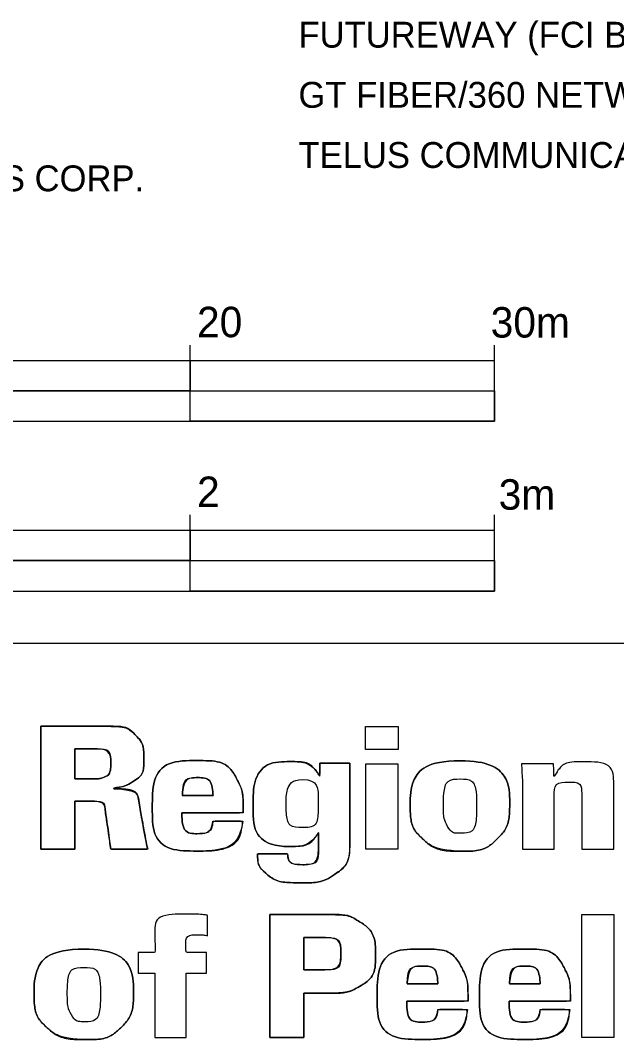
# Model space of a CAD drawing. Extents: x 613360 to 613780, y 4825621 to 4825911.
# Drawn here: x 613737.07 to 613756.65, y 4825658.5 to 4825691.97 of the extents above; entities that cross this region are included whole.
import ezdxf

# ---------------------------------------------------------------- set-up
doc = ezdxf.new("R2010")
doc.units = 0
for name, color, linetype in [('G-ANNO-BAR', 7, 'Continuous'), ('G-ANNO-TEXT', 7, 'Continuous'), ('G-TTLB-LOGO', 7, 'Continuous'), ('G-TTLB-OTLN', 7, 'Continuous')]:
    doc.layers.add(name, color=color, linetype=linetype)

msp = doc.modelspace()

# ---------------------------------------------------------------- linework, layer by layer
at = {"layer": 'G-ANNO-BAR'}
for p, q in [((613742.645, 4825678.805), (613742.645, 4825681.305)), ((613752.645, 4825678.805), (613752.645, 4825681.305)), ((613712.645, 4825680.805), (613752.645, 4825680.805)), ((613712.645, 4825679.805), (613752.645, 4825679.805)), ((613712.645, 4825678.805), (613752.645, 4825678.805)), ((613742.646, 4825673.229), (613742.646, 4825675.729)), ((613752.646, 4825673.229), (613752.646, 4825675.729)), ((613712.646, 4825675.229), (613752.646, 4825675.229)), ((613712.646, 4825674.229), (613752.646, 4825674.229)), ((613712.646, 4825673.229), (613752.646, 4825673.229))]:
    msp.add_line(p, q, dxfattribs=at)
for points in [[(613732.645, 4825680.805), (613742.645, 4825680.805), (613742.645, 4825679.805), (613732.645, 4825679.805)], [(613742.645, 4825679.805), (613752.645, 4825679.805), (613752.645, 4825678.805), (613742.645, 4825678.805)], [(613732.646, 4825675.229), (613742.646, 4825675.229), (613742.646, 4825674.229), (613732.646, 4825674.229)], [(613742.646, 4825674.229), (613752.646, 4825674.229), (613752.646, 4825673.229), (613742.646, 4825673.229)]]:
    msp.add_lwpolyline(points, close=True, dxfattribs=at)
at = {"layer": 'G-TTLB-LOGO'}
for p, q in [((613748.408, 4825668.781), (613749.482, 4825668.781)), ((613748.408, 4825668.032), (613748.408, 4825668.781)), ((613749.482, 4825668.781), (613749.482, 4825668.032)), ((613749.482, 4825668.032), (613748.408, 4825668.032)), ((613748.419, 4825667.562), (613749.47, 4825667.562)), ((613748.419, 4825664.754), (613748.419, 4825667.562)), ((613749.47, 4825667.562), (613749.47, 4825664.754)), ((613740.143, 4825666.762), (613740.143, 4825666.74)), ((613742.387, 4825666.516), (613743.399, 4825666.516)), ((613744.389, 4825665.946), (613742.375, 4825665.946)), ((613743.393, 4825665.672), (613744.372, 4825665.672)), ((613746.865, 4825664.928), (613746.865, 4825665.297)), ((613741.251, 4825664.754), (613740.037, 4825664.754)), ((613744.857, 4825664.604), (613745.847, 4825664.604)), ((613749.47, 4825664.754), (613748.419, 4825664.754)), ((613755.504, 4825662.605), (613756.556, 4825662.605)), ((613755.504, 4825658.567), (613755.504, 4825662.605)), ((613756.556, 4825662.605), (613756.556, 4825658.567)), ((613749.77, 4825660.329), (613750.782, 4825660.329)), ((613753.132, 4825660.329), (613754.144, 4825660.329)), ((613751.772, 4825659.758), (613749.759, 4825659.758)), ((613755.134, 4825659.758), (613753.12, 4825659.758)), ((613750.777, 4825659.484), (613751.756, 4825659.484)), ((613754.138, 4825659.484), (613755.117, 4825659.484)), ((613756.556, 4825658.567), (613755.504, 4825658.567))]:
    msp.add_line(p, q, dxfattribs=at)
for points in [[(613739.332, 4825666.332), (613738.862, 4825666.332), (613738.862, 4825664.754), (613737.738, 4825664.754), (613737.738, 4825668.792), (613739.606, 4825668.792)], [(613748.408, 4825668.781), (613749.482, 4825668.781), (613749.482, 4825668.032), (613748.408, 4825668.032), (613748.408, 4825668.781)], [(613739.282, 4825668.049), (613738.862, 4825668.049), (613738.862, 4825667.059), (613739.282, 4825667.059)], [(613746.899, 4825667.154), (613746.899, 4825667.579), (613747.889, 4825667.579), (613747.889, 4825664.961)], [(613748.419, 4825667.562), (613749.47, 4825667.562), (613749.47, 4825664.754), (613748.419, 4825664.754), (613748.419, 4825667.562)], [(613747.108, 4825660.027), (613746.381, 4825660.021), (613746.381, 4825658.567), (613745.257, 4825658.567), (613745.257, 4825662.605), (613747.113, 4825662.605)], [(613755.504, 4825662.605), (613756.556, 4825662.605), (613756.556, 4825658.567), (613755.504, 4825658.567), (613755.504, 4825662.605)], [(613746.873, 4825661.855), (613746.381, 4825661.855), (613746.381, 4825660.793), (613746.878, 4825660.793)]]:
    msp.add_lwpolyline(points, dxfattribs=at)
for points in [[(613737.738, 4825668.792), (613737.738, 4825668.792), (613739.606, 4825668.792), (613739.606, 4825668.792), (613740.333, 4825668.792), (613740.607, 4825668.748), (613740.848, 4825668.502), (613740.971, 4825668.378), (613741.127, 4825668.155), (613741.127, 4825667.719), (613741.127, 4825667.277), (613740.949, 4825667.086), (613740.758, 4825666.969), (613740.501, 4825666.807), (613740.255, 4825666.779), (613740.143, 4825666.762), (613740.143, 4825666.762), (613740.143, 4825666.74), (613740.143, 4825666.74), (613740.926, 4825666.717), (613740.942, 4825666.373), (613741.06, 4825665.75), (613741.112, 4825665.478), (613741.202, 4825664.949), (613741.251, 4825664.754), (613741.251, 4825664.754), (613740.037, 4825664.754), (613740.037, 4825664.754), (613740.017, 4825664.897), (613739.96, 4825665.318), (613739.913, 4825665.628), (613739.84, 4825666.112), (613739.836, 4825666.332), (613739.332, 4825666.332), (613739.332, 4825666.332), (613738.862, 4825666.332), (613738.862, 4825666.332), (613738.862, 4825666.332), (613738.862, 4825664.754), (613738.862, 4825664.754), (613738.862, 4825664.754), (613737.738, 4825664.754), (613737.738, 4825664.754), (613737.738, 4825664.754), (613737.738, 4825668.792), (613737.738, 4825668.792)], [(613739.606, 4825668.792), (613740.333, 4825668.792), (613740.607, 4825668.748), (613740.848, 4825668.502), (613740.971, 4825668.378), (613741.127, 4825668.155), (613741.127, 4825667.719), (613741.127, 4825667.277), (613740.949, 4825667.086), (613740.758, 4825666.969), (613740.501, 4825666.807), (613740.255, 4825666.779), (613740.143, 4825666.762)], [(613738.862, 4825667.059), (613738.862, 4825667.059), (613739.282, 4825667.059), (613739.282, 4825667.059), (613739.528, 4825667.059), (613739.651, 4825667.059), (613739.746, 4825667.092), (613739.992, 4825667.17), (613740.043, 4825667.422), (613740.043, 4825667.551), (613740.043, 4825668.049), (613739.606, 4825668.049), (613739.282, 4825668.049), (613739.282, 4825668.049), (613738.862, 4825668.049), (613738.862, 4825668.049), (613738.862, 4825668.049), (613738.862, 4825667.059), (613738.862, 4825667.059)], [(613739.282, 4825667.059), (613739.528, 4825667.059), (613739.651, 4825667.059), (613739.746, 4825667.092), (613739.992, 4825667.17), (613740.043, 4825667.422), (613740.043, 4825667.551), (613740.043, 4825668.049), (613739.606, 4825668.049), (613739.282, 4825668.049)], [(613742.375, 4825665.946), (613742.375, 4825665.794), (613742.375, 4825665.263), (613742.912, 4825665.263), (613743.192, 4825665.263), (613743.365, 4825665.409), (613743.393, 4825665.672), (613743.393, 4825665.672), (613744.372, 4825665.672), (613744.372, 4825665.672), (613744.294, 4825664.967), (613743.634, 4825664.693), (613742.907, 4825664.693), (613741.928, 4825664.693), (613741.402, 4825665.185), (613741.402, 4825666.114), (613741.402, 4825667.053), (613741.861, 4825667.663), (613742.896, 4825667.663), (613743.678, 4825667.663), (613744.042, 4825667.344), (613744.232, 4825666.947), (613744.355, 4825666.706), (613744.389, 4825666.438), (613744.389, 4825665.946), (613744.389, 4825665.946), (613742.375, 4825665.946), (613742.375, 4825665.946)], [(613744.372, 4825665.672), (613744.294, 4825664.967), (613743.634, 4825664.693), (613742.907, 4825664.693), (613741.928, 4825664.693), (613741.402, 4825665.185), (613741.402, 4825666.114), (613741.402, 4825667.053), (613741.861, 4825667.663), (613742.896, 4825667.663), (613743.678, 4825667.663), (613744.042, 4825667.344), (613744.232, 4825666.947), (613744.355, 4825666.706), (613744.389, 4825666.438), (613744.389, 4825665.946)], [(613747.889, 4825667.579), (613747.889, 4825667.579), (613747.889, 4825664.961), (613747.889, 4825664.961), (613747.889, 4825664.626), (613747.822, 4825664.229), (613747.441, 4825663.96), (613747.201, 4825663.787), (613746.86, 4825663.647), (613746.284, 4825663.647), (613745.965, 4825663.647), (613745.433, 4825663.692), (613745.115, 4825663.977), (613744.869, 4825664.195), (613744.863, 4825664.458), (613744.857, 4825664.604), (613744.857, 4825664.604), (613745.847, 4825664.604), (613745.847, 4825664.604), (613745.853, 4825664.391), (613746.004, 4825664.245), (613746.306, 4825664.245), (613746.832, 4825664.245), (613746.865, 4825664.626), (613746.865, 4825664.928), (613746.865, 4825664.928), (613746.865, 4825665.297), (613746.865, 4825665.297), (613746.58, 4825664.872), (613746.121, 4825664.844), (613745.959, 4825664.844), (613745.366, 4825664.844), (613744.712, 4825665.213), (613744.712, 4825666.236), (613744.712, 4825666.997), (613745.115, 4825667.629), (613745.97, 4825667.629), (613746.513, 4825667.629), (613746.759, 4825667.377), (613746.899, 4825667.154), (613746.899, 4825667.154), (613746.899, 4825667.579), (613746.899, 4825667.579), (613746.899, 4825667.579), (613747.889, 4825667.579), (613747.889, 4825667.579)], [(613746.865, 4825665.297), (613746.58, 4825664.872), (613746.121, 4825664.844), (613745.959, 4825664.844), (613745.366, 4825664.844), (613744.712, 4825665.213), (613744.712, 4825666.236), (613744.712, 4825666.997), (613745.115, 4825667.629), (613745.97, 4825667.629), (613746.513, 4825667.629), (613746.759, 4825667.377), (613746.899, 4825667.154)], [(613751.518, 4825667.657), (613752.43, 4825667.657), (613753.14, 4825667.198), (613753.14, 4825666.203), (613753.14, 4825665.794), (613753.023, 4825665.381), (613752.732, 4825665.09), (613752.497, 4825664.861), (613752.15, 4825664.687), (613751.574, 4825664.687), (613750.953, 4825664.687), (613750.551, 4825664.838), (613750.277, 4825665.101), (613749.952, 4825665.409), (613749.874, 4825665.828), (613749.874, 4825666.169), (613749.874, 4825667.031), (613750.405, 4825667.657), (613751.518, 4825667.657)], [(613751.218, 4825664.706), (613750.793, 4825664.754), (613750.495, 4825664.892), (613750.277, 4825665.101), (613749.952, 4825665.409), (613749.874, 4825665.828), (613749.874, 4825666.169), (613749.874, 4825667.031), (613750.405, 4825667.657), (613751.518, 4825667.657)], [(613751.518, 4825667.657), (613752.43, 4825667.657), (613753.14, 4825667.198), (613753.14, 4825666.203), (613753.14, 4825665.794), (613753.023, 4825665.381), (613752.732, 4825665.09), (613752.497, 4825664.861), (613752.15, 4825664.687), (613751.574, 4825664.687), (613751.447, 4825664.687), (613751.328, 4825664.694), (613751.218, 4825664.706)], [(613753.558, 4825666.964), (613753.558, 4825666.964), (613753.53, 4825667.562), (613753.53, 4825667.562), (613753.53, 4825667.562), (613754.581, 4825667.562), (613754.581, 4825667.562), (613754.581, 4825667.562), (613754.593, 4825667.131), (613754.593, 4825667.131), (613754.721, 4825667.344), (613754.945, 4825667.623), (613755.527, 4825667.623), (613756.556, 4825667.623), (613756.556, 4825666.841), (613756.556, 4825666.454), (613756.556, 4825666.454), (613756.556, 4825664.754), (613756.556, 4825664.754), (613756.556, 4825664.754), (613755.504, 4825664.754), (613755.504, 4825664.754), (613755.504, 4825664.754), (613755.504, 4825666.365), (613755.504, 4825666.365), (613755.504, 4825666.561), (613755.504, 4825666.958), (613755.074, 4825666.958), (613754.604, 4825666.958), (613754.604, 4825666.466), (613754.604, 4825666.365), (613754.604, 4825666.365), (613754.604, 4825664.754), (613754.604, 4825664.754), (613754.604, 4825664.754), (613753.558, 4825664.754), (613753.558, 4825664.754), (613753.558, 4825664.754), (613753.558, 4825666.964), (613753.558, 4825666.964)], [(613753.558, 4825666.964), (613753.558, 4825666.964), (613753.53, 4825667.562), (613753.53, 4825667.562), (613753.53, 4825667.562), (613754.581, 4825667.562), (613754.581, 4825667.562), (613754.581, 4825667.562), (613754.593, 4825667.131), (613754.593, 4825667.131), (613754.721, 4825667.344), (613754.945, 4825667.623), (613755.527, 4825667.623), (613756.556, 4825667.623), (613756.556, 4825666.841), (613756.556, 4825666.454), (613756.556, 4825666.454), (613756.556, 4825664.754), (613756.556, 4825664.754), (613756.556, 4825664.754), (613755.504, 4825664.754), (613755.504, 4825664.754), (613755.504, 4825664.754), (613755.504, 4825666.365), (613755.504, 4825666.365), (613755.504, 4825666.561), (613755.504, 4825666.958), (613755.074, 4825666.958), (613754.604, 4825666.958), (613754.604, 4825666.466), (613754.604, 4825666.365), (613754.604, 4825666.365), (613754.604, 4825664.754), (613754.604, 4825664.754), (613754.604, 4825664.754), (613753.558, 4825664.754), (613753.558, 4825664.754), (613753.558, 4825664.754), (613753.558, 4825666.964), (613753.558, 4825666.964)], [(613743.399, 4825666.516), (613743.388, 4825666.678), (613743.354, 4825667.103), (613742.896, 4825667.103), (613742.437, 4825667.103), (613742.398, 4825666.65), (613742.387, 4825666.516), (613742.387, 4825666.516), (613743.399, 4825666.516), (613743.399, 4825666.516)], [(613743.399, 4825666.516), (613743.388, 4825666.678), (613743.354, 4825667.103), (613742.896, 4825667.103), (613742.437, 4825667.103), (613742.398, 4825666.65), (613742.387, 4825666.516)], [(613746.339, 4825667.042), (613745.987, 4825667.042), (613745.797, 4825666.717), (613745.797, 4825666.248), (613745.797, 4825665.951), (613745.864, 4825665.465), (613746.328, 4825665.465), (613746.832, 4825665.465), (613746.849, 4825666.057), (613746.849, 4825666.259), (613746.849, 4825666.404), (613746.849, 4825667.042), (613746.339, 4825667.042)], [(613746.339, 4825667.042), (613745.987, 4825667.042), (613745.797, 4825666.717), (613745.797, 4825666.248), (613745.797, 4825665.951), (613745.864, 4825665.465), (613746.328, 4825665.465), (613746.832, 4825665.465), (613746.849, 4825666.057), (613746.849, 4825666.259), (613746.849, 4825666.404), (613746.849, 4825667.042), (613746.339, 4825667.042)], [(613751.099, 4825665.498), (613751.222, 4825665.286), (613751.412, 4825665.275), (613751.507, 4825665.275), (613751.966, 4825665.275), (613752.055, 4825665.772), (613752.055, 4825666.164), (613752.055, 4825666.65), (613751.938, 4825667.059), (613751.518, 4825667.059), (613751.054, 4825667.059), (613750.965, 4825666.583), (613750.965, 4825666.164), (613750.965, 4825665.979), (613750.981, 4825665.705), (613751.099, 4825665.498)], [(613751.099, 4825665.498), (613751.222, 4825665.286), (613751.412, 4825665.275), (613751.507, 4825665.275), (613751.966, 4825665.275), (613752.055, 4825665.772), (613752.055, 4825666.164), (613752.055, 4825666.65), (613751.938, 4825667.059), (613751.518, 4825667.059), (613751.054, 4825667.059), (613750.965, 4825666.583), (613750.965, 4825666.164), (613750.965, 4825665.979), (613750.981, 4825665.705), (613751.099, 4825665.498)], [(613740.143, 4825666.74), (613740.926, 4825666.717), (613740.942, 4825666.373), (613741.06, 4825665.75), (613741.112, 4825665.478), (613741.202, 4825664.949), (613741.251, 4825664.754)], [(613740.037, 4825664.754), (613740.017, 4825664.897), (613739.96, 4825665.318), (613739.913, 4825665.628), (613739.84, 4825666.112), (613739.836, 4825666.332), (613739.332, 4825666.332)], [(613742.375, 4825665.946), (613742.375, 4825665.794), (613742.375, 4825665.263), (613742.912, 4825665.263), (613743.192, 4825665.263), (613743.365, 4825665.409), (613743.393, 4825665.672)], [(613747.889, 4825664.961), (613747.889, 4825664.626), (613747.822, 4825664.229), (613747.441, 4825663.96), (613747.201, 4825663.787), (613746.86, 4825663.647), (613746.284, 4825663.647), (613745.965, 4825663.647), (613745.433, 4825663.692), (613745.115, 4825663.977), (613744.869, 4825664.195), (613744.863, 4825664.458), (613744.857, 4825664.604)], [(613745.847, 4825664.604), (613745.853, 4825664.391), (613746.004, 4825664.245), (613746.306, 4825664.245), (613746.832, 4825664.245), (613746.865, 4825664.626), (613746.865, 4825664.928)], [(613743.215, 4825661.911), (613743.17, 4825661.923), (613743.064, 4825661.945), (613742.924, 4825661.945), (613742.493, 4825661.945), (613742.505, 4825661.598), (613742.51, 4825661.363), (613742.51, 4825661.363), (613743.187, 4825661.363), (613743.187, 4825661.363), (613743.187, 4825661.363), (613743.187, 4825660.681), (613743.187, 4825660.681), (613743.187, 4825660.681), (613742.51, 4825660.681), (613742.51, 4825660.681), (613742.51, 4825660.681), (613742.51, 4825658.567), (613742.51, 4825658.567), (613742.51, 4825658.567), (613741.481, 4825658.567), (613741.481, 4825658.567), (613741.481, 4825658.567), (613741.481, 4825660.681), (613741.481, 4825660.681), (613741.481, 4825660.681), (613740.939, 4825660.681), (613740.939, 4825660.681), (613740.939, 4825660.681), (613740.939, 4825661.363), (613740.939, 4825661.363), (613740.939, 4825661.363), (613741.498, 4825661.363), (613741.498, 4825661.363), (613741.481, 4825662.034), (613741.493, 4825662.622), (613742.594, 4825662.622), (613742.88, 4825662.622), (613743.098, 4825662.599), (613743.215, 4825662.588), (613743.215, 4825662.588), (613743.215, 4825661.911), (613743.215, 4825661.911)], [(613743.215, 4825661.911), (613743.17, 4825661.923), (613743.064, 4825661.945), (613742.924, 4825661.945), (613742.493, 4825661.945), (613742.505, 4825661.598), (613742.51, 4825661.363), (613742.51, 4825661.363), (613743.187, 4825661.363), (613743.187, 4825661.363), (613743.187, 4825661.363), (613743.187, 4825660.681), (613743.187, 4825660.681), (613743.187, 4825660.681), (613742.51, 4825660.681), (613742.51, 4825660.681), (613742.51, 4825660.681), (613742.51, 4825658.567), (613742.51, 4825658.567), (613742.51, 4825658.567), (613741.481, 4825658.567), (613741.481, 4825658.567), (613741.481, 4825658.567), (613741.481, 4825660.681), (613741.481, 4825660.681), (613741.481, 4825660.681), (613740.939, 4825660.681), (613740.939, 4825660.681), (613740.939, 4825660.681), (613740.939, 4825661.363), (613740.939, 4825661.363), (613740.939, 4825661.363), (613741.498, 4825661.363), (613741.498, 4825661.363), (613741.481, 4825662.034), (613741.493, 4825662.622), (613742.594, 4825662.622), (613742.88, 4825662.622), (613743.098, 4825662.599), (613743.215, 4825662.588), (613743.215, 4825662.588), (613743.215, 4825661.911), (613743.215, 4825661.911)], [(613745.257, 4825662.605), (613745.257, 4825662.605), (613747.113, 4825662.605), (613747.113, 4825662.605), (613747.427, 4825662.605), (613747.835, 4825662.605), (613748.165, 4825662.398), (613748.506, 4825662.191), (613748.735, 4825661.828), (613748.735, 4825661.302), (613748.735, 4825660.592), (613748.282, 4825660.284), (613748.126, 4825660.2), (613747.812, 4825660.027), (613747.326, 4825660.027), (613747.108, 4825660.027), (613747.108, 4825660.027), (613746.381, 4825660.021), (613746.381, 4825660.021), (613746.381, 4825660.021), (613746.381, 4825658.567), (613746.381, 4825658.567), (613746.381, 4825658.567), (613745.257, 4825658.567), (613745.257, 4825658.567), (613745.257, 4825658.567), (613745.257, 4825662.605), (613745.257, 4825662.605)], [(613747.113, 4825662.605), (613747.427, 4825662.605), (613747.835, 4825662.605), (613748.165, 4825662.398), (613748.506, 4825662.191), (613748.735, 4825661.828), (613748.735, 4825661.302), (613748.735, 4825660.592), (613748.282, 4825660.284), (613748.126, 4825660.2), (613747.812, 4825660.027), (613747.326, 4825660.027), (613747.108, 4825660.027)], [(613746.381, 4825660.793), (613746.381, 4825660.793), (613746.878, 4825660.793), (613746.878, 4825660.793), (613747.153, 4825660.793), (613747.594, 4825660.793), (613747.594, 4825661.335), (613747.594, 4825661.828), (613747.197, 4825661.855), (613746.873, 4825661.855), (613746.873, 4825661.855), (613746.381, 4825661.855), (613746.381, 4825661.855), (613746.381, 4825661.855), (613746.381, 4825660.793), (613746.381, 4825660.793)], [(613746.878, 4825660.793), (613747.153, 4825660.793), (613747.594, 4825660.793), (613747.594, 4825661.335), (613747.594, 4825661.828), (613747.197, 4825661.855), (613746.873, 4825661.855)], [(613739.164, 4825661.469), (613740.076, 4825661.469), (613740.786, 4825661.011), (613740.786, 4825660.016), (613740.786, 4825659.607), (613740.669, 4825659.193), (613740.378, 4825658.902), (613740.143, 4825658.673), (613739.796, 4825658.5), (613739.22, 4825658.5), (613738.6, 4825658.5), (613738.197, 4825658.651), (613737.923, 4825658.914), (613737.598, 4825659.221), (613737.52, 4825659.641), (613737.52, 4825659.982), (613737.52, 4825660.843), (613738.051, 4825661.469), (613739.164, 4825661.469)], [(613738.865, 4825658.519), (613738.44, 4825658.567), (613738.141, 4825658.705), (613737.923, 4825658.914), (613737.598, 4825659.221), (613737.52, 4825659.641), (613737.52, 4825659.982), (613737.52, 4825660.843), (613738.051, 4825661.469), (613739.164, 4825661.469)], [(613739.164, 4825661.469), (613740.076, 4825661.469), (613740.786, 4825661.011), (613740.786, 4825660.016), (613740.786, 4825659.607), (613740.669, 4825659.193), (613740.378, 4825658.902), (613740.143, 4825658.673), (613739.796, 4825658.5), (613739.22, 4825658.5), (613739.093, 4825658.5), (613738.975, 4825658.506), (613738.865, 4825658.519)], [(613749.759, 4825659.758), (613749.759, 4825659.607), (613749.759, 4825659.076), (613750.296, 4825659.076), (613750.575, 4825659.076), (613750.749, 4825659.221), (613750.777, 4825659.484), (613750.777, 4825659.484), (613751.756, 4825659.484), (613751.756, 4825659.484), (613751.677, 4825658.779), (613751.017, 4825658.505), (613750.29, 4825658.505), (613749.311, 4825658.505), (613748.786, 4825658.998), (613748.786, 4825659.926), (613748.786, 4825660.865), (613749.244, 4825661.475), (613750.279, 4825661.475), (613751.062, 4825661.475), (613751.426, 4825661.156), (613751.616, 4825660.759), (613751.739, 4825660.519), (613751.772, 4825660.25), (613751.772, 4825659.758), (613751.772, 4825659.758), (613749.759, 4825659.758), (613749.759, 4825659.758)], [(613751.756, 4825659.484), (613751.677, 4825658.779), (613751.017, 4825658.505), (613750.29, 4825658.505), (613749.311, 4825658.505), (613748.786, 4825658.998), (613748.786, 4825659.926), (613748.786, 4825660.865), (613749.244, 4825661.475), (613750.279, 4825661.475), (613751.062, 4825661.475), (613751.426, 4825661.156), (613751.616, 4825660.759), (613751.739, 4825660.519), (613751.772, 4825660.25), (613751.772, 4825659.758)], [(613753.12, 4825659.758), (613753.12, 4825659.607), (613753.12, 4825659.076), (613753.657, 4825659.076), (613753.937, 4825659.076), (613754.11, 4825659.221), (613754.138, 4825659.484), (613754.138, 4825659.484), (613755.117, 4825659.484), (613755.117, 4825659.484), (613755.039, 4825658.779), (613754.379, 4825658.505), (613753.652, 4825658.505), (613752.673, 4825658.505), (613752.147, 4825658.998), (613752.147, 4825659.926), (613752.147, 4825660.865), (613752.606, 4825661.475), (613753.641, 4825661.475), (613754.424, 4825661.475), (613754.787, 4825661.156), (613754.977, 4825660.759), (613755.1, 4825660.519), (613755.134, 4825660.25), (613755.134, 4825659.758), (613755.134, 4825659.758), (613753.12, 4825659.758), (613753.12, 4825659.758)], [(613755.117, 4825659.484), (613755.039, 4825658.779), (613754.379, 4825658.505), (613753.652, 4825658.505), (613752.673, 4825658.505), (613752.147, 4825658.998), (613752.147, 4825659.926), (613752.147, 4825660.865), (613752.606, 4825661.475), (613753.641, 4825661.475), (613754.424, 4825661.475), (613754.787, 4825661.156), (613754.977, 4825660.759), (613755.1, 4825660.519), (613755.134, 4825660.25), (613755.134, 4825659.758)], [(613738.745, 4825659.311), (613738.868, 4825659.098), (613739.058, 4825659.087), (613739.153, 4825659.087), (613739.612, 4825659.087), (613739.701, 4825659.585), (613739.701, 4825659.976), (613739.701, 4825660.463), (613739.584, 4825660.871), (613739.164, 4825660.871), (613738.7, 4825660.871), (613738.611, 4825660.396), (613738.611, 4825659.976), (613738.611, 4825659.792), (613738.627, 4825659.518), (613738.745, 4825659.311)], [(613738.745, 4825659.311), (613738.868, 4825659.098), (613739.058, 4825659.087), (613739.153, 4825659.087), (613739.612, 4825659.087), (613739.701, 4825659.585), (613739.701, 4825659.976), (613739.701, 4825660.463), (613739.584, 4825660.871), (613739.164, 4825660.871), (613738.7, 4825660.871), (613738.611, 4825660.396), (613738.611, 4825659.976), (613738.611, 4825659.792), (613738.627, 4825659.518), (613738.745, 4825659.311)], [(613750.782, 4825660.329), (613750.771, 4825660.491), (613750.738, 4825660.916), (613750.279, 4825660.916), (613749.821, 4825660.916), (613749.781, 4825660.463), (613749.77, 4825660.329), (613749.77, 4825660.329), (613750.782, 4825660.329), (613750.782, 4825660.329)], [(613750.782, 4825660.329), (613750.771, 4825660.491), (613750.738, 4825660.916), (613750.279, 4825660.916), (613749.821, 4825660.916), (613749.781, 4825660.463), (613749.77, 4825660.329)], [(613754.144, 4825660.329), (613754.133, 4825660.491), (613754.099, 4825660.916), (613753.641, 4825660.916), (613753.182, 4825660.916), (613753.143, 4825660.463), (613753.132, 4825660.329), (613753.132, 4825660.329), (613754.144, 4825660.329), (613754.144, 4825660.329)], [(613754.144, 4825660.329), (613754.133, 4825660.491), (613754.099, 4825660.916), (613753.641, 4825660.916), (613753.182, 4825660.916), (613753.143, 4825660.463), (613753.132, 4825660.329)], [(613749.759, 4825659.758), (613749.759, 4825659.607), (613749.759, 4825659.076), (613750.296, 4825659.076), (613750.575, 4825659.076), (613750.749, 4825659.221), (613750.777, 4825659.484)], [(613753.12, 4825659.758), (613753.12, 4825659.607), (613753.12, 4825659.076), (613753.657, 4825659.076), (613753.937, 4825659.076), (613754.11, 4825659.221), (613754.138, 4825659.484)]]:
    msp.add_open_spline(points, degree=3, dxfattribs=at)
at = {"layer": 'G-TTLB-OTLN'}
msp.add_line((613774.178, 4825671.507), (613710.777, 4825671.507), dxfattribs=at)

# ---------------------------------------------------------------- texts
at = {"layer": 'G-ANNO-BAR'}
for s, p in [('20', (613742.871, 4825681.567)), ('30m', (613752.516, 4825681.556)), ('2', (613742.872, 4825675.991)), ('3m', (613752.778, 4825675.903))]:
    msp.add_text(s, height=1, rotation=360, dxfattribs=at).set_placement(p)
at = {"layer": 'G-ANNO-TEXT'}
for s, p in [('FUTUREWAY (FCI BROADBAND)', (613746.202, 4825691.077)), ('GT FIBER/360 NETWORK INC.', (613746.202, 4825689.102)), ('TELUS COMMUNICATION', (613746.202, 4825687.127)), ('PEARSON INTERNATIONAL FUEL FACILITIES CORP.', (613712.651, 4825686.36))]:
    msp.add_text(s, height=0.85, dxfattribs=at).set_placement(p)

doc.saveas('drawing.dxf')
